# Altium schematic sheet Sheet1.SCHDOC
size 296 x 209 mm; SheetNumber: 1; SheetTotal: 1
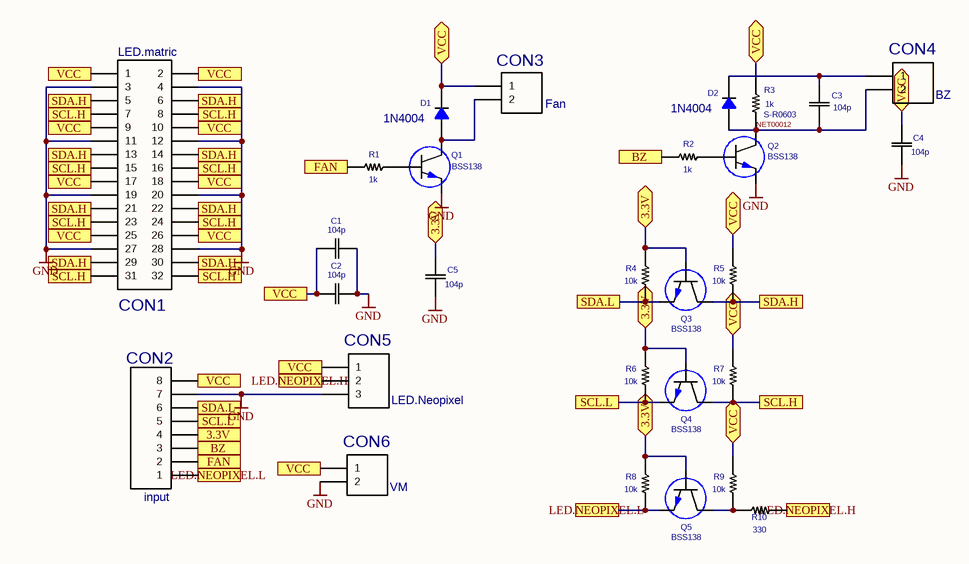
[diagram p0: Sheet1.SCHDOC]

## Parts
C1  value 104p  [CC0603]  (hidden comment: S-104P)
C2  value 104p  [CC0603]  (hidden comment: S-104P)
C3  value 104p  [CC0603]  (hidden comment: S-104P)
C4  value 104p  [CC0603]  (hidden comment: S-104P)
C5  value 104p  [CC0603]  (hidden comment: S-104P)
CON1  value LED.matric  [HDR2X16H]  (hidden comment: HEADER_16X2H)
CON2  value input  [HDR1X8H]  (hidden comment: HEADER_8H)
CON3  value Fan  [HDR1X2H]  (hidden comment: HEADER_2H)
CON4  value BZ  [HDR1X2H]  (hidden comment: HEADER_2H)
CON5  value LED.Neopixel  [HDR1X3H]  (hidden comment: HEADER_3H)
CON6  value VM  [HDR1X2H]  (hidden comment: HEADER_2H)
D1  value 1N4004  [D2010]  (hidden comment: S-1N4004)
D2  value 1N4004  [D2010]  (hidden comment: S-1N4004)
Q1  value BSS138  [SOT-23]  (hidden comment: S-2SC2412)
Q2  value BSS138  [SOT-23]  (hidden comment: S-2SC2412)
Q3  value BSS138  [SOT-23]  (hidden comment: S-2SC2412)
Q4  value BSS138  [SOT-23]  (hidden comment: S-2SC2412)
Q5  value BSS138  [SOT-23]  (hidden comment: S-2SC2412)
R1  value 1k  [R0603]  (hidden comment: S-R0603)
R2  value 1k  [R0603]  (hidden comment: S-R0603)
R3  S-R0603  value 1k  [R0603]
R4  value 10k  [R0603]  (hidden comment: S-R0603)
R5  value 10k  [R0603]  (hidden comment: S-R0603)
R6  value 10k  [R0603]  (hidden comment: S-R0603)
R7  value 10k  [R0603]  (hidden comment: S-R0603)
R8  value 10k  [R0603]  (hidden comment: S-R0603)
R9  value 10k  [R0603]  (hidden comment: S-R0603)
R10  value 330  [R0603]  (hidden comment: S-R0603)

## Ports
3.3V, BZ, FAN, LED.NEOPIXEL.H, LED.NEOPIXEL.L, SCL.H, SCL.L, SDA.H, SDA.L, VCC

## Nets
GND: C1.2 C2.2 C4.1 C5.1 CON1.3 CON1.4 CON1.11 CON1.12 CON1.19 CON1.20 CON1.27 CON1.28 CON2.7 CON5.3 CON6.2 Q1.3 Q2.3
3.3V: C5.2 CON2.4 Q3.1 Q4.1 Q5.1 R4.B R6.B R8.B ; port 3.3V
BZ: CON2.3 R2.A ; port BZ
FAN: CON2.2 R1.A ; port FAN
LED.NEOPIXEL.H: CON5.2 R10.A ; port LED.NEOPIXEL.H
LED.NEOPIXEL.L: CON2.1 Q5.3 R8.A ; port LED.NEOPIXEL.L
NET00012: C3.1 CON4.2 D2.2 Q2.2 R3.A
SCL.H: CON1.7 CON1.8 CON1.15 CON1.16 CON1.23 CON1.24 CON1.31 CON1.32 Q4.2 R7.A ; port SCL.H
SCL.L: CON2.5 Q4.3 R6.A ; port SCL.L
SDA.H: CON1.5 CON1.6 CON1.13 CON1.14 CON1.21 CON1.22 CON1.29 CON1.30 Q3.2 R5.A ; port SDA.H
SDA.L: CON2.6 Q3.3 R4.A ; port SDA.L
VCC: C1.1 C2.1 C3.2 C4.2 CON1.1 CON1.2 CON1.9 CON1.10 CON1.17 CON1.18 CON1.25 CON1.26 CON2.8 CON3.1 CON4.1 CON5.1 CON6.1 D1.1 D2.1 R3.B R5.B R7.B R9.B ; port VCC
NetCON3_2: CON3.2 D1.2 Q1.2
NetQ1_1: Q1.1 R1.B
NetQ2_1: Q2.1 R2.B
NetQ5_2: Q5.2 R9.A R10.B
